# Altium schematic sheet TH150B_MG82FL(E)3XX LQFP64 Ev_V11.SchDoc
size 279 x 193 mm; PageSetup: Record=PageOptions|CenterHorizontal=True|CenterVertical=True|PrintScale=1.02|XCorrection=1.00|YCorrection=1.00|PrintKind=0|BorderSize=5000000|LeftOffset=0|BottomOffset=0|Orientation=2|PaperLength=1000|PaperWidth=1000|Scale=100|PaperSource=7|PrintQuality=-4|MediaType=1|DitherType=10|PaperKind=A4 (210 x 297 mm)|PrintScaleMode=1
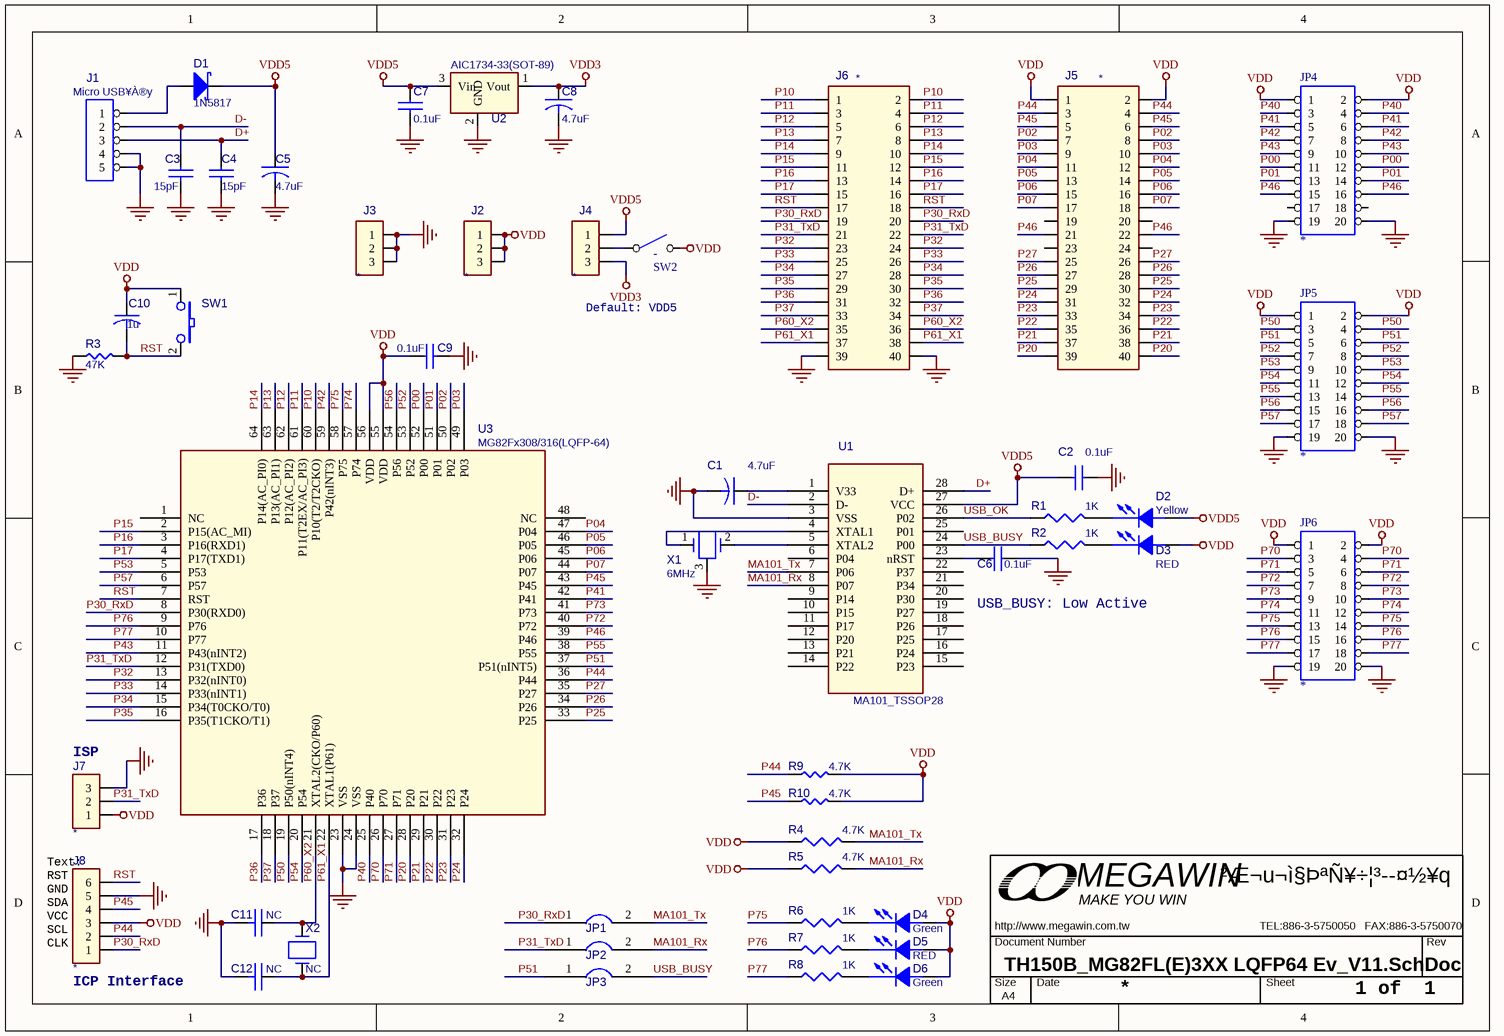
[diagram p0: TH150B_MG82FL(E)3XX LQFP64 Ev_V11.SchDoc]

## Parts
C1  4.7uF  [0805C]
C2  0.1uF  [0805C]
C3  15pF  [0805C]
C4  15pF  [0805C]
C5  4.7uF  [1206C]
C6  0.1uF  [0805C]
C7  0.1uF  [0805C]
C8  4.7uF  [0805C]
C9  0.1uF  [0805C]
C10  1u  [0805C]
C11  NC  [0805C]
C12  NC  [0805C]
D1  1N5817  [D5817_SMD_1]
D2  Yellow  [0805D]
D3  RED  [0805D]
D4  Green  [0805D]
D5  RED  [0805D]
D6  Green  [0805D]
J1  Micro USB¥À®y  [JACK_USB_SMD290X220P065]
J2  *  [PS3P254]
J3  *  [PS3P254]
J4  *  [JUMP3_SMD]
J5  *  [PS20X2P254]
J6  *  [PS20X2P254]
J7  *  [PS3P254f_90]
J8  *  [PS6P254F_90]
JP1  JUMPER2  [ps2p254]  (value not drawn)
JP2  JUMPER2  [ps2p254]  (value not drawn)
JP3  JUMPER2  [ps2p254]  (value not drawn)
JP4  *  [PS10X2P254]
JP5  *  [PS10X2P254]
JP6  *  [PS10X2P254]
MW1  OrgName: ²Æ¬u¬ì§ÞªÑ¥÷¦³­­¤½¥q  OrgAddr1: MEGAWIN  OrgAddr3: TEL:886-3-5750050   FAX:886-3-5750070  Page Size: A4  [MEGAWIN_T]  (hidden comment: MW-A4)  (no BOM)
R1  1K  [0805R]
R2  1K  [0805R]
R3  47K  [0805R]
R4  4.7K  [0805R]
R5  4.7K  [0805R]
R6  1K  [0805R]
R7  1K  [0805R]
R8  1K  [0805R]
R9  4.7K  [0805R]
R10  4.7K  [0805R]
SW1  SW TACT-SPST  [SW_T_2P]  (value not drawn)
SW2  -  [DIP2_SW]
U1  MA101_TSSOP28  [TSSOP28_170P065]
U2  AIC1734-33(SOT-89)  [SOT89]
U3  MG82Fx308/316(LQFP-64)  [QFP64_7X7P040]
X1  6MHz  [X3P]
X2  NC  [X49U]

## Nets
GND_POWER: C1.2 C2.1 C3.2 C4.2 C5.2 C6.1 C7.2 C8.2 C9.2 C11.2 C12.2 J1.4 J1.5 J3.1 J3.2 J3.3 J6.39 J6.40 J7.3 J8.5 JP4.19 JP4.20 JP5.19 JP5.20 JP6.19 JP6.20 R3.1 U1.3(VSS) U2.2(GND) U3.23(VSS) U3.24(VSS) X1.3
VDD: C9.1 C10.1(POS) D3.1(ANODE) D4.1(ANODE) D5.1(ANODE) D6.1(ANODE) J2.1 J2.2 J2.3 J5.1 J5.2 J7.1 J8.3 JP4.1 JP4.2 JP5.1 JP5.2 JP6.1 JP6.2 R4.1 R5.1 R9.2 R10.2 SW1.1 SW2.2(NO) U3.55(VDD) U3.56(VDD)
VDD3: C8.1 J4.3 U2.1(Vout)
VDD5: C2.2 C5.1 C7.1 D1.2(K) D2.1(ANODE) J4.1 U1.27(VCC) U2.3(Vin)
D+: C4.1 J1.3 U1.28(D+)
D-: C3.1 J1.2 U1.2(D-)
MA101_Rx: JP2.2 R5.2 U1.8(P07)
MA101_Tx: JP1.2 R4.2 U1.7(P06)
P00: JP4.11 JP4.12 U3.52(P00)
P01: JP4.13 JP4.14 U3.51(P01)
P02: J5.7 J5.8 U3.50(P02)
P03: J5.9 J5.10 U3.49(P03)
P04: J5.11 J5.12 U3.47(P04)
P05: J5.13 J5.14 U3.46(P05)
P06: J5.15 J5.16 U3.45(P06)
P07: J5.17 J5.18 U3.44(P07)
P10: J6.1 J6.2 U3.60(P10(T2/T2CKO))
P11: J6.3 J6.4 U3.61(P11(T2EX/AC_PI3))
P12: J6.5 J6.6 U3.62(P12(AC_PI2))
P13: J6.7 J6.8 U3.63(P13(AC_PI1))
P14: J6.9 J6.10 U3.64(P14(AC_PI0))
P15: J6.11 J6.12 U3.2(P15(AC_MI))
P16: J6.13 J6.14 U3.3(P16(RXD1))
P17: J6.15 J6.16 U3.4(P17(TXD1))
P20: J5.39 J5.40 U3.28(P20)
P21: J5.37 J5.38 U3.29(P21)
P22: J5.35 J5.36 U3.30(P22)
P23: J5.33 J5.34 U3.31(P23)
P24: J5.31 J5.32 U3.32(P24)
P25: J5.29 J5.30 U3.33(P25)
P26: J5.27 J5.28 U3.34(P26)
P27: J5.25 J5.26 U3.35(P27)
P30_RxD: J6.19 J6.20 J8.1 JP1.1 U3.8(P30(RXD0))
P31_TxD: J6.21 J6.22 J7.2 JP2.1 U3.12(P31(TXD0))
P32: J6.23 J6.24 U3.13(P32(nINT0))
P33: J6.25 J6.26 U3.14(P33(nINT1))
P34: J6.27 J6.28 U3.15(P34(T0CKO/T0))
P35: J6.29 J6.30 U3.16(P35(T1CKO/T1))
P36: J6.31 J6.32 U3.17(P36)
P37: J6.33 J6.34 U3.18(P37)
P40: JP4.3 JP4.4 U3.25(P40)
P41: JP4.5 JP4.6 U3.42(P41)
P42: JP4.7 JP4.8 U3.59(P42(nINT3))
P43: JP4.9 JP4.10 U3.11(P43(nINT2))
P44: J5.3 J5.4 J8.2 R9.1 U3.36(P44)
P45: J5.5 J5.6 J8.4 R10.1 U3.43(P45)
P46: J5.21 J5.22 JP4.15 JP4.16 U3.39(P46)
P50: JP5.3 JP5.4 U3.19(P50(nINT4))
P51: JP3.1 JP5.5 JP5.6 U3.37(P51(nINT5))
P52: JP5.7 JP5.8 U3.53(P52)
P53: JP5.9 JP5.10 U3.5(P53)
P54: JP5.11 JP5.12 U3.20(P54)
P55: JP5.13 JP5.14 U3.38(P55)
P56: JP5.15 JP5.16 U3.54(P56)
P57: JP5.17 JP5.18 U3.6(P57)
P60_X2: C11.1 J6.35 J6.36 U3.21(XTAL2(CKO/P60)) X2.1
P61_X1: C12.1 J6.37 J6.38 U3.22(XTAL1(P61)) X2.2
P70: JP6.3 JP6.4 U3.26(P70)
P71: JP6.5 JP6.6 U3.27(P71)
P72: JP6.7 JP6.8 U3.40(P72)
P73: JP6.9 JP6.10 U3.41(P73)
P74: JP6.11 JP6.12 U3.57(P74)
P75: JP6.13 JP6.14 R6.1 U3.58(P75)
P76: JP6.15 JP6.16 R7.1 U3.9(P76)
P77: JP6.17 JP6.18 R8.1 U3.10(P77)
RST: C10.2(NEG) J6.17 J6.18 J8.6 R3.2 SW1.2 U3.7(RST)
USB_BUSY: JP3.2 R2.1 U1.24(P00)
USB_OK: R1.1 U1.26(P02)
NetC1_1: C1.1 U1.1(V33)
NetC6_2: C6.2 U1.23(nRST)
NetD1_1: D1.1(A) J1.1
NetD2_2: D2.2(CATHODE) R1.2
NetD3_2: D3.2(CATHODE) R2.2
NetD4_2: D4.2(CATHODE) R6.2
NetD5_2: D5.2(CATHODE) R7.2
NetD6_2: D6.2(CATHODE) R8.2
NetJ4_2: J4.2 SW2.1(COMMON)
NetU1_4: U1.4(XTAL1) X1.1
NetU1_5: U1.5(XTAL2) X1.2

Not connected (* = marked no-connect by the designer): J5 19 20 23 24; JP4 17 18; U1 6(P04) 9(P14) 10(P15) 11(P17) 12(P20) 13(P21) 14(P22) 15(P23) 16(P24) 17(P25) 18(P26) 19(P27) 20(P30) 21(P34) 22(P37) 25(P01); U3 1(NC) 48(NC)

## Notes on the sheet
- Default: VDD5
- USB_BUSY: Low Active
- (near J7) ISP
- (near J8) Text:
  RST
  GND
  SDA
  VCC
  SCL
  CLK
- (near J8) ICP Interface
- 1 of  1

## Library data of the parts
C1 C5 C8 = CAP
C2-C4 C6 C7 C9 = CAP NP
C10 = C
C11 C12 = C NP
D1 = DIODE_ZD: Schottky Diode
D2-D6 = LED
J1 = CON5: Connector
J2-J4 J7 = CON3
J5 J6 = CON40A
J8 = CON6
JP4-JP6 = CON10X2
R1 R2 R4-R8 = R_Dup1
R3 R9 R10 = R
SW2 = SW-2
U2 = AIC1734-33(SOT-89)_0
U3 = MG82Fx3xx_0
X1 = CRYSTAL_RC
X2 = CRYSTAL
